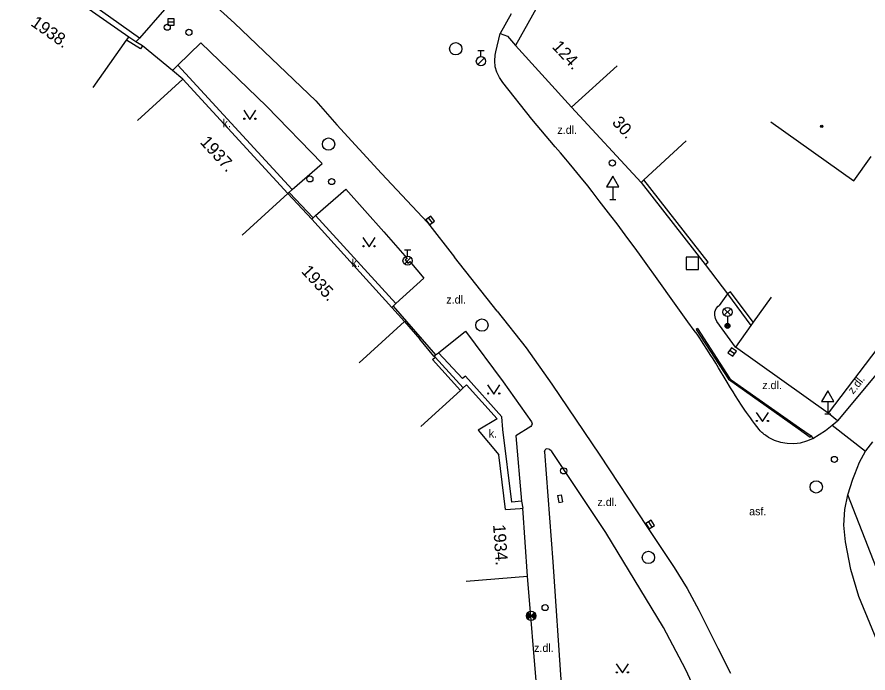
# Model space of a CAD drawing. Extents: x -538441 to -536770, y -1181008 to -1179809.
# Drawn here: x -537871.2 to -537802.1, y -1180501.9 to -1180448.5 of the extents above; entities that cross this region are included whole.
import ezdxf

# ---------------------------------------------------------------- set-up
doc = ezdxf.new("R2010")
doc.units = 0
for name, color, linetype in [('Vrstva 10', 7, 'Continuous'), ('Vrstva 11', 7, 'Continuous'), ('Vrstva 17', 7, 'Continuous'), ('Vrstva 24', 7, 'Continuous'), ('Vrstva 26', 7, 'Continuous'), ('Vrstva 27', 7, 'Continuous'), ('Vrstva 28', 7, 'Continuous'), ('Vrstva 31', 7, 'Continuous'), ('Vrstva 33', 7, 'Continuous'), ('Vrstva 34', 7, 'Continuous'), ('Vrstva 36', 7, 'Continuous'), ('Vrstva 39', 7, 'Continuous'), ('Vrstva 40', 7, 'Continuous'), ('Vrstva 47', 7, 'Continuous'), ('Vrstva 5', 7, 'Continuous'), ('Vrstva 54', 7, 'Continuous'), ('Vrstva 7', 7, 'Continuous'), ('Vrstva 8', 7, 'Continuous')]:
    doc.layers.add(name, color=color, linetype=linetype)

msp = doc.modelspace()

# ---------------------------------------------------------------- linework, layer by layer
at = {"layer": 'Vrstva 10'}
for p, q in [((-537857.93, -1180445), (-537853.53, -1180449.04)), ((-537831.054, -1180448.291), (-537831.93, -1180449.89)), ((-537853.53, -1180449.04), (-537846.9, -1180455.35)), ((-537832.3, -1180451.39), (-537831.93, -1180449.89)), ((-537846.9, -1180455.35), (-537845.21, -1180457.31)), ((-537845.21, -1180457.31), (-537841.58, -1180461.26)), ((-537827.039, -1180459.591), (-537827.464, -1180459.095)), ((-537841.58, -1180461.26), (-537837.84, -1180465.25)), ((-537837.84, -1180465.25), (-537835.65, -1180468.07)), ((-537832.18, -1180472.46), (-537835.65, -1180468.07)), ((-537817.651, -1180471.981), (-537819.323, -1180469.649)), ((-537800.175, -1180476.112), (-537804.56, -1180481.36)), ((-537827.76, -1180478.39), (-537823.855, -1180484.147)), ((-537804.988, -1180481.716), (-537802.278, -1180483.84)), ((-537823.855, -1180484.147), (-537820.02, -1180489.95)), ((-537800.41, -1180501.508), (-537802.812, -1180495.63))]:
    msp.add_line(p, q, dxfattribs=at)
for points in [[(-537831.74, -1180453.86), (-537832.01, -1180453.472), (-537832.211, -1180453.044), (-537832.337, -1180452.588), (-537832.384, -1180452.117), (-537832.352, -1180451.645), (-537832.3, -1180451.39)], [(-537827.464, -1180459.095), (-537829.382, -1180456.838), (-537831.74, -1180453.86)], [(-537825.971, -1180460.873), (-537826.34, -1180460.425), (-537826.619, -1180460.09), (-537827.039, -1180459.591)], [(-537824.837, -1180462.278), (-537825.483, -1180461.473), (-537825.971, -1180460.873)], [(-537819.323, -1180469.649), (-537819.952, -1180468.775), (-537820.505, -1180468.011), (-537820.99, -1180467.345), (-537821.416, -1180466.763), (-537821.79, -1180466.254), (-537822.45, -1180465.368), (-537822.949, -1180464.707), (-537823.325, -1180464.212), (-537823.895, -1180463.474), (-537824.47, -1180462.74), (-537824.837, -1180462.278)], [(-537832.18, -1180472.46), (-537829.841, -1180475.445), (-537827.76, -1180478.39)], [(-537813.586, -1180478.099), (-537814.208, -1180477.063), (-537814.442, -1180476.677), (-537814.648, -1180476.339), (-537814.83, -1180476.045), (-537815.154, -1180475.532), (-537815.401, -1180475.15), (-537815.59, -1180474.865), (-537815.734, -1180474.653), (-537815.955, -1180474.335), (-537816.18, -1180474.02), (-537816.693, -1180473.312), (-537817.651, -1180471.981)], [(-537810.17, -1180482.68), (-537810.372, -1180482.568), (-537810.444, -1180482.516), (-537810.507, -1180482.468), (-537810.612, -1180482.38), (-537810.689, -1180482.31), (-537810.744, -1180482.256), (-537810.824, -1180482.17), (-537810.9, -1180482.08), (-537811.095, -1180481.833), (-537811.28, -1180481.593), (-537811.455, -1180481.359), (-537811.621, -1180481.132), (-537811.779, -1180480.911), (-537811.929, -1180480.696), (-537812.072, -1180480.488), (-537812.344, -1180480.083), (-537812.593, -1180479.702), (-537812.821, -1180479.343), (-537813.031, -1180479.007), (-537813.226, -1180478.691), (-537813.586, -1180478.099)], [(-537806.55, -1180482.79), (-537805.526, -1180482.157), (-537804.988, -1180481.716), (-537804.56, -1180481.36)], [(-537810.17, -1180482.68), (-537809.686, -1180482.926), (-537809.17, -1180483.098), (-537808.635, -1180483.192), (-537808.092, -1180483.207), (-537807.553, -1180483.142), (-537807.029, -1180482.999), (-537806.55, -1180482.79)], [(-537803.139, -1180485.704), (-537802.766, -1180484.715), (-537802.278, -1180483.84), (-537802.248, -1180483.794), (-537801.69, -1180483.066)], [(-537804.029, -1180489.855), (-537803.947, -1180488.58), (-537803.717, -1180487.368), (-537803.311, -1180486.112), (-537803.139, -1180485.704)], [(-537802.812, -1180495.63), (-537803.468, -1180493.44), (-537803.891, -1180491.193), (-537804.029, -1180489.855)], [(-537820.02, -1180489.95), (-537817.811, -1180493.295), (-537816.761, -1180494.999), (-537815.804, -1180496.755)], [(-537815.804, -1180496.755), (-537814.527, -1180499.308), (-537814.265, -1180499.831), (-537813.25, -1180501.86)]]:
    msp.add_lwpolyline(points, dxfattribs=at)
at = {"layer": 'Vrstva 11'}
for p, q in [((-537861.24, -1180450.26), (-537867.46, -1180445.82)), ((-537859.2, -1180447.95), (-537861.24, -1180450.26)), ((-537861.24, -1180450.26), (-537861.52, -1180450.562)), ((-537856.26, -1180450.66), (-537858.11, -1180452.46)), ((-537850.91, -1180455.79), (-537856.26, -1180450.66)), ((-537858.11, -1180452.46), (-537858.554, -1180452.904)), ((-537848.84, -1180462.57), (-537858.11, -1180452.46)), ((-537846.41, -1180460.44), (-537850.91, -1180455.79)), ((-537848.84, -1180462.57), (-537846.41, -1180460.44)), ((-537849.19, -1180462.9), (-537848.84, -1180462.57)), ((-537847.24, -1180464.98), (-537846.93, -1180464.68)), ((-537846.93, -1180464.68), (-537840.41, -1180471.84)), ((-537813.48, -1180471.05), (-537814.16, -1180471.98)), ((-537840.41, -1180471.84), (-537840.74, -1180472.15)), ((-537812.84, -1180475.38), (-537814.34, -1180473.28)), ((-537834.77, -1180474.09), (-537831.69, -1180478.19)), ((-537813.4, -1180477.97), (-537807.75, -1180481.99)), ((-537813.18, -1180478.04), (-537807.63, -1180481.93)), ((-537831.69, -1180478.19), (-537829.39, -1180481.45)), ((-537804.56, -1180481.36), (-537805.31, -1180480.74)), ((-537830.993, -1180487.986), (-537831.73, -1180482.06)), ((-537829.46, -1180481.83), (-537830.66, -1180482.59)), ((-537807.63, -1180481.93), (-537806.69, -1180482.59)), ((-537830.66, -1180482.59), (-537830.22, -1180487.89)), ((-537806.69, -1180482.59), (-537806.55, -1180482.79)), ((-537828.34, -1180483.89), (-537827.67, -1180492.82)), ((-537823.357, -1180490.448), (-537827.74, -1180483.87)), ((-537800.436, -1180495.786), (-537803.717, -1180487.368)), ((-537830.22, -1180487.89), (-537830.993, -1180487.986)), ((-537830.22, -1180487.89), (-537830.11, -1180488.47)), ((-537818.67, -1180498.16), (-537823.357, -1180490.448)), ((-537827.67, -1180492.82), (-537826.98, -1180502.8)), ((-537816.902, -1180501.549), (-537818.67, -1180498.16)), ((-537814.496, -1180506.595), (-537816.902, -1180501.549))]:
    msp.add_line(p, q, dxfattribs=at)
for points in [[(-537831.93, -1180449.89), (-537831.36, -1180450.11), (-537830.71, -1180450.85)], [(-537846.93, -1180464.68), (-537844.48, -1180462.53), (-537841.39, -1180466)], [(-537841.39, -1180466), (-537839.5, -1180468.16), (-537839.66, -1180468.28), (-537839.44, -1180468.54), (-537839.27, -1180468.43), (-537838.15, -1180469.78), (-537840.41, -1180471.84)], [(-537814.34, -1180473.28), (-537814.469, -1180473.04), (-537814.5, -1180472.79), (-537814.499, -1180472.501), (-537814.397, -1180472.248), (-537814.226, -1180472.035), (-537814.16, -1180471.98)], [(-537815.93, -1180473.86), (-537816.03, -1180473.94), (-537813.4, -1180477.97)], [(-537815.93, -1180473.86), (-537813.32, -1180477.89), (-537813.18, -1180478.04)], [(-537837.32, -1180476.1), (-537837.19, -1180476), (-537836.95, -1180475.83), (-537834.77, -1180474.09)], [(-537831.73, -1180482.06), (-537831.82, -1180481.03), (-537834.76, -1180477.73), (-537835.01, -1180477.92), (-537836.95, -1180475.83)], [(-537829.39, -1180481.45), (-537829.353, -1180481.602), (-537829.395, -1180481.752), (-537829.46, -1180481.83)], [(-537807.75, -1180481.99), (-537806.76, -1180482.68), (-537806.69, -1180482.59)], [(-537828.34, -1180483.89), (-537828.29, -1180483.72), (-537828.205, -1180483.642), (-537828.12, -1180483.61)], [(-537828.12, -1180483.61), (-537827.928, -1180483.678), (-537827.777, -1180483.813), (-537827.74, -1180483.87)]]:
    msp.add_lwpolyline(points, dxfattribs=at)
at = {"layer": 'Vrstva 17'}
for p, q in [((-537829.804, -1180497.241), (-537829.607, -1180497.043)), ((-537829.801, -1180497.167), (-537829.642, -1180497.008)), ((-537829.796, -1180497.303), (-537829.572, -1180497.079)), ((-537829.779, -1180497.357), (-537829.536, -1180497.114)), ((-537829.773, -1180497.068), (-537829.677, -1180496.973)), ((-537829.756, -1180497.405), (-537829.501, -1180497.149)), ((-537829.728, -1180497.447), (-537829.465, -1180497.185)), ((-537829.695, -1180497.485), (-537829.165, -1180496.955)), ((-537829.695, -1180496.955), (-537829.165, -1180497.485)), ((-537829.395, -1180497.255), (-537829.132, -1180496.993)), ((-537829.359, -1180497.291), (-537829.104, -1180497.035)), ((-537829.324, -1180497.326), (-537829.081, -1180497.083)), ((-537829.288, -1180497.361), (-537829.064, -1180497.137)), ((-537829.253, -1180497.397), (-537829.056, -1180497.199)), ((-537829.218, -1180497.432), (-537829.059, -1180497.273)), ((-537829.183, -1180497.467), (-537829.087, -1180497.372))]:
    msp.add_line(p, q, dxfattribs=at)
msp.add_circle((-537829.43, -1180497.22), 0.375, dxfattribs=at)
at = {"layer": 'Vrstva 24'}
for p, q in [((-537827.28, -1180487.43), (-537826.984, -1180487.382)), ((-537827.28, -1180487.43), (-537827.19, -1180487.99)), ((-537826.984, -1180487.382), (-537826.894, -1180487.942)), ((-537827.19, -1180487.99), (-537826.894, -1180487.942))]:
    msp.add_line(p, q, dxfattribs=at)
at = {"layer": 'Vrstva 26'}
msp.add_lwpolyline([(-537816.85, -1180469.06), (-537815.85, -1180469.06), (-537815.85, -1180468.06), (-537816.85, -1180468.06)], close=True, dxfattribs=at)
at = {"layer": 'Vrstva 27'}
for p, q in [((-537858.92, -1180448.95), (-537858.42, -1180448.95)), ((-537837.778, -1180464.881), (-537837.474, -1180465.279)), ((-537813.304, -1180475.625), (-537812.896, -1180475.915)), ((-537819.901, -1180489.582), (-537819.633, -1180490.004))]:
    msp.add_line(p, q, dxfattribs=at)
for points in [[(-537858.92, -1180449.2), (-537858.42, -1180449.2), (-537858.42, -1180448.7), (-537858.92, -1180448.7)], [(-537837.976, -1180465.033), (-537837.673, -1180465.43), (-537837.276, -1180465.127), (-537837.579, -1180464.73)], [(-537813.449, -1180475.829), (-537813.041, -1180476.119), (-537812.751, -1180475.711), (-537813.159, -1180475.421)], [(-537820.112, -1180489.716), (-537819.844, -1180490.138), (-537819.422, -1180489.87), (-537819.69, -1180489.448)]]:
    msp.add_lwpolyline(points, close=True, dxfattribs=at)
for centre in [(-537835.556, -1180451.128), (-537845.88, -1180458.88), (-537833.42, -1180473.59), (-537806.28, -1180486.739), (-537819.91, -1180492.47)]:
    msp.add_circle(centre, 0.5, dxfattribs=at)
at = {"layer": 'Vrstva 28'}
for p, q in [((-537833.762, -1180452.412), (-537833.232, -1180451.882)), ((-537833.754, -1180451.265), (-537833.254, -1180451.265)), ((-537833.504, -1180451.765), (-537833.504, -1180451.265)), ((-537839.71, -1180467.475), (-537839.21, -1180467.475)), ((-537839.46, -1180467.975), (-537839.46, -1180467.475)), ((-537839.718, -1180468.622), (-537839.188, -1180468.092))]:
    msp.add_line(p, q, dxfattribs=at)
for centre, radius in [((-537857.22, -1180449.79), 0.25), ((-537833.504, -1180452.14), 0.375), ((-537822.83, -1180460.41), 0.25), ((-537847.4, -1180461.7), 0.25), ((-537845.63, -1180461.92), 0.25), ((-537839.46, -1180468.35), 0.375), ((-537804.795, -1180484.504), 0.25), ((-537826.79, -1180485.43), 0.25), ((-537828.29, -1180496.54), 0.25)]:
    msp.add_circle(centre, radius, dxfattribs=at)
at = {"layer": 'Vrstva 31'}
msp.add_circle((-537858.98, -1180449.38), 0.25, dxfattribs=at)
at = {"layer": 'Vrstva 33'}
for p, q in [((-537813.745, -1180472.79), (-537813.215, -1180472.26)), ((-537813.745, -1180472.26), (-537813.215, -1180472.79)), ((-537813.48, -1180472.9), (-537813.48, -1180473.65))]:
    msp.add_line(p, q, dxfattribs=at)
for centre, radius in [((-537813.48, -1180472.525), 0.375), ((-537813.48, -1180473.65), 0.2), ((-537813.48, -1180473.65), 0.145), ((-537813.48, -1180473.65), 0.0876)]:
    msp.add_circle(centre, radius, dxfattribs=at)
at = {"layer": 'Vrstva 34'}
for p, q in [((-537822.8, -1180462.352), (-537822.8, -1180463.37)), ((-537823.05, -1180463.37), (-537822.55, -1180463.37)), ((-537805.34, -1180479.792), (-537805.34, -1180480.81)), ((-537805.59, -1180480.81), (-537805.09, -1180480.81))]:
    msp.add_line(p, q, dxfattribs=at)
for points in [[(-537823.3, -1180462.352), (-537822.3, -1180462.352), (-537822.8, -1180461.486)], [(-537805.84, -1180479.792), (-537804.84, -1180479.792), (-537805.34, -1180478.926)]]:
    msp.add_lwpolyline(points, close=True, dxfattribs=at)
at = {"layer": 'Vrstva 36'}
for points in [[(-537852.773, -1180456.114), (-537852.273, -1180456.864), (-537851.773, -1180456.114)], [(-537843.093, -1180466.477), (-537842.593, -1180467.227), (-537842.093, -1180466.477)], [(-537832.963, -1180478.441), (-537832.463, -1180479.191), (-537831.963, -1180478.441)], [(-537811.149, -1180480.679), (-537810.649, -1180481.429), (-537810.149, -1180480.679)], [(-537822.516, -1180501.107), (-537822.016, -1180501.857), (-537821.516, -1180501.107)]]:
    msp.add_lwpolyline(points, dxfattribs=at)
for centre in [(-537852.723, -1180456.814), (-537851.824, -1180456.814), (-537843.043, -1180467.177), (-537842.144, -1180467.177), (-537832.913, -1180479.141), (-537832.014, -1180479.141), (-537811.099, -1180481.379), (-537810.2, -1180481.379), (-537822.466, -1180501.807), (-537821.567, -1180501.807)]:
    msp.add_circle(centre, 0.05, dxfattribs=at)
at = {"layer": 'Vrstva 39'}
for radius in [0.09, 0.0398]:
    msp.add_circle((-537805.834, -1180457.435), radius, dxfattribs=at)
at = {"layer": 'Vrstva 5'}
for p, q in [((-537864.99, -1180454.277), (-537862.283, -1180450.436)), ((-537862.283, -1180450.436), (-537862.11, -1180450.19)), ((-537830.71, -1180450.85), (-537826.15, -1180455.87)), ((-537822.445, -1180452.512), (-537826.15, -1180455.87)), ((-537861.407, -1180456.968), (-537857.72, -1180453.59)), ((-537826.15, -1180455.87), (-537820.5, -1180461.99)), ((-537809.973, -1180457.07), (-537803.225, -1180461.874)), ((-537816.826, -1180458.598), (-537820.279, -1180461.786)), ((-537803.225, -1180461.874), (-537801.812, -1180459.889)), ((-537820.279, -1180461.786), (-537820.5, -1180461.99)), ((-537852.884, -1180466.27), (-537849.19, -1180462.9)), ((-537847.24, -1180464.98), (-537849.19, -1180462.9)), ((-537840.74, -1180472.15), (-537847.24, -1180464.98)), ((-537809.94, -1180471.307), (-537811.398, -1180473.354)), ((-537839.71, -1180473.29), (-537840.74, -1180472.15)), ((-537843.404, -1180476.66), (-537839.71, -1180473.29)), ((-537811.581, -1180473.612), (-537812.84, -1180475.38)), ((-537811.398, -1180473.354), (-537811.581, -1180473.612)), ((-537805.31, -1180480.74), (-537812.84, -1180475.38)), ((-537800.75, -1180474.75), (-537805.31, -1180480.74)), ((-537835.165, -1180478.894), (-537834.944, -1180478.693)), ((-537834.944, -1180478.693), (-537834.678, -1180478.451)), ((-537832.19, -1180481.19), (-537834.678, -1180478.451)), ((-537838.379, -1180481.813), (-537835.165, -1180478.894)), ((-537832.19, -1180481.19), (-537833.728, -1180482.125)), ((-537833.728, -1180482.125), (-537832.06, -1180484.12)), ((-537831.507, -1180488.566), (-537832.06, -1180484.12)), ((-537831.507, -1180488.566), (-537830.309, -1180488.484)), ((-537830.309, -1180488.484), (-537830.11, -1180488.47)), ((-537829.729, -1180493.992), (-537830.11, -1180488.47)), ((-537834.712, -1180494.403), (-537829.729, -1180493.992)), ((-537828.94, -1180503.568), (-537829.729, -1180493.992))]:
    msp.add_line(p, q, dxfattribs=at)
for points in [[(-537825.9, -1180442.29), (-537826.794, -1180443.881), (-537827.301, -1180444.783), (-537830.71, -1180450.85)], [(-537862.11, -1180450.19), (-537867.738, -1180446.225), (-537871.18, -1180443.8)], [(-537849.19, -1180462.9), (-537857.72, -1180453.59)]]:
    msp.add_lwpolyline(points, dxfattribs=at)
at = {"layer": 'Vrstva 54'}
for p, q in [((-537847.13, -1180464.87), (-537849.04, -1180462.84)), ((-537840.63, -1180472.05), (-537837.19, -1180476))]:
    msp.add_line(p, q, dxfattribs=at)
at = {"layer": 'Vrstva 7'}
for p, q in [((-537861.16, -1180451.144), (-537862.283, -1180450.436)), ((-537861, -1180450.89), (-537861.16, -1180451.144)), ((-537820.5, -1180461.99), (-537815.29, -1180468.65)), ((-537815.054, -1180468.465), (-537820.279, -1180461.786)), ((-537815.29, -1180468.65), (-537815.054, -1180468.465)), ((-537811.398, -1180473.354), (-537813.238, -1180470.871)), ((-537839.71, -1180473.29), (-537838.465, -1180474.74)), ((-537837.441, -1180476.391), (-537837.22, -1180476.19)), ((-537837.441, -1180476.391), (-537835.165, -1180478.894)), ((-537837.22, -1180476.19), (-537834.944, -1180478.693))]:
    msp.add_line(p, q, dxfattribs=at)
for points in [[(-537861, -1180450.89), (-537861.52, -1180450.562), (-537862.11, -1180450.19)], [(-537813.238, -1180470.871), (-537813.48, -1180471.05), (-537811.581, -1180473.612)]]:
    msp.add_lwpolyline(points, dxfattribs=at)
at = {"layer": 'Vrstva 8'}
msp.add_line((-537815.29, -1180468.65), (-537813.48, -1180471.05), dxfattribs=at)
for points in [[(-537857.72, -1180453.59), (-537858.554, -1180452.904), (-537861, -1180450.89)], [(-537837.22, -1180476.19), (-537837.32, -1180476.1), (-537838.465, -1180474.74)]]:
    msp.add_lwpolyline(points, dxfattribs=at)

# ---------------------------------------------------------------- texts
at = {"layer": 'Vrstva 40'}
for s, p in [('k.', (-537854.49, -1180457.507)), ('z.dl.', (-537827.297, -1180458.043)), ('k.', (-537844.016, -1180468.859)), ('z.dl.', (-537836.318, -1180471.837)), ('z.dl.', (-537810.659, -1180478.788)), ('k.', (-537832.87, -1180482.723)), ('z.dl.', (-537824.047, -1180488.287)), ('asf.', (-537811.728, -1180489.04)), ('z.dl.', (-537829.186, -1180500.144))]:
    msp.add_text(s, height=0.65, dxfattribs=at).set_placement(p)
msp.add_text('z.dl.', height=0.65, rotation=51.83682, dxfattribs=at).set_placement((-537803.27, -1180479.24))
at = {"layer": 'Vrstva 47'}
for s, rotation, p in [('1938.', 324.83452, (-537870.128, -1180449.198)), ('124.', 312.71328, (-537827.787, -1180451.004)), ('30.', 312.71328, (-537822.915, -1180457.164)), ('1937.', 312.49651, (-537856.375, -1180458.758)), ('1935.', 312.37782, (-537848.148, -1180469.255)), ('1934.', 273.94696, (-537832.523, -1180489.813))]:
    msp.add_text(s, height=1, rotation=rotation, dxfattribs=at).set_placement(p)

doc.saveas('drawing.dxf')
